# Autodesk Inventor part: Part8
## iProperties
Created: 2001-11
Part Number: Part8
Document SubType Name: Modeling
Designer: hassen
Density: 1 g/cm^3
Control State: 0
Master: False
Checked Out: False
Shininess: 64.0
Length Units: 11269
Angle Units: 11279
Time Units: 11290
Mass Units: 11283
Length Display Precision: 3
Angle Display Precision: 2
Density: 0.0
Volumn: 0.0
Area: 0.0
PropertySet Name: Model Information
Author: hassen
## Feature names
1. Revolution1
